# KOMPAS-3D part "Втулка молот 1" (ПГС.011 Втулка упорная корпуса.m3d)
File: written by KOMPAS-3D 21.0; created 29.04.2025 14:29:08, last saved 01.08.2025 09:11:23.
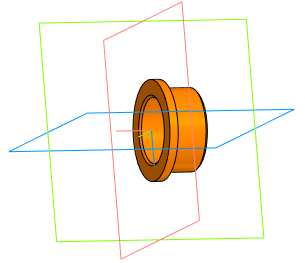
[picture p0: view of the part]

Document properties: Полное имя файла: C:\Users\User\Desktop\ПЕРСПЕКТИВА кд\Модель\ПГС.011 Втулка упорная корпуса.m3d; Автор: User

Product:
- Part/product: Втулка молот 1
    Масса: 0.01036
    Форматы листов документа: A4

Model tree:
1. Эскиз:1
2. Элемент вращения:1
     Угол 1 = 360
3. Фаска:1  (with: Элемент вращения:1)
     Угол = 45; Длина 1 = 0.5; Длина 2 = 0.5

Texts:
  Линейный размер с обрывом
